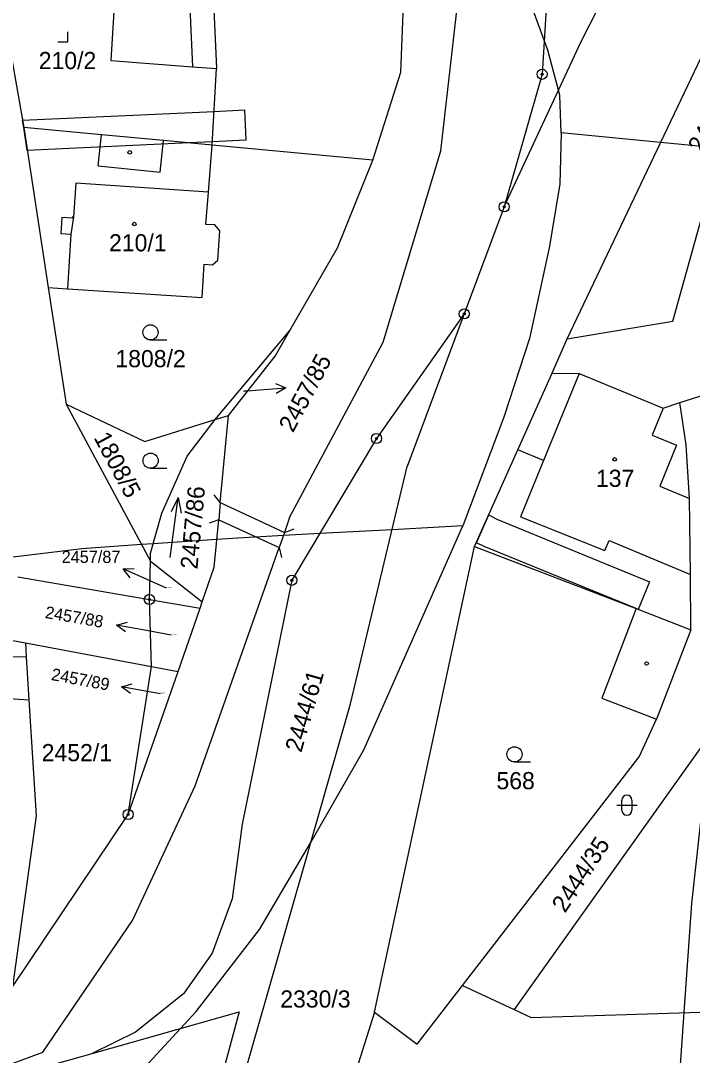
# Model space of a CAD drawing. Extents: x -546762 to -540209, y -1046851 to -1035694.
# Drawn here: x -542623.1 to -542556.7, y -1039379.4 to -1039277.1 of the extents above; entities that cross this region are included whole.
import ezdxf

# ---------------------------------------------------------------- set-up
doc = ezdxf.new("R2010")
doc.units = 0
for name, color, linetype in [('Vrstva 1', 7, 'Continuous'), ('Vrstva 16', 7, 'Continuous'), ('Vrstva 18', 7, 'Continuous'), ('Vrstva 19', 7, 'Continuous'), ('Vrstva 24', 7, 'Continuous'), ('Vrstva 25', 7, 'Continuous'), ('Vrstva 26', 7, 'Continuous'), ('Vrstva 3', 7, 'Continuous'), ('Vrstva 30', 7, 'Continuous'), ('Vrstva 37', 7, 'Continuous'), ('Vrstva 4', 7, 'Continuous'), ('Vrstva 52', 7, 'Continuous'), ('Vrstva 6', 7, 'Continuous')]:
    doc.layers.add(name, color=color, linetype=linetype)

msp = doc.modelspace()

# ---------------------------------------------------------------- linework, layer by layer
at = {"layer": 'Vrstva 1'}
for p, q in [((-542570.97, -1039273.17), (-542571.53, -1039282.43)), ((-542571.53, -1039282.43), (-542575.28, -1039295.54)), ((-542575.28, -1039295.54), (-542579.22, -1039306.11)), ((-542596.46, -1039307.75), (-542591.77, -1039299.59)), ((-542579.22, -1039306.11), (-542587.9, -1039318.45)), ((-542579.22, -1039306.11), (-542584.86, -1039321.23)), ((-542603.84, -1039316.58), (-542596.46, -1039307.75)), ((-542597.93, -1039310.3), (-542596.46, -1039307.75)), ((-542610.81, -1039318.73), (-542603.84, -1039316.58)), ((-542606.63, -1039320.18), (-542603.84, -1039316.58)), ((-542603.84, -1039316.58), (-542602.55, -1039316.18)), ((-542587.9, -1039318.45), (-542596.27, -1039332.47)), ((-542609.14, -1039325.83), (-542606.63, -1039320.18)), ((-542610.26, -1039329.78), (-542609.14, -1039325.83)), ((-542610.26, -1039330.56), (-542610.26, -1039329.78)), ((-542610.36, -1039334.36), (-542610.26, -1039330.56)), ((-542596.27, -1039332.47), (-542601.17, -1039356.59)), ((-542610.16, -1039340.99), (-542610.36, -1039334.36)), ((-542622.62, -1039338.66), (-542610.16, -1039340.99)), ((-542612.46, -1039355.63), (-542610.16, -1039340.99)), ((-542610.16, -1039340.99), (-542607.53, -1039341.48)), ((-542601.17, -1039356.59), (-542602.16, -1039363.96)), ((-542602.16, -1039363.96), (-542604.15, -1039369.33)), ((-542604.15, -1039369.33), (-542606.97, -1039373.35)), ((-542606.97, -1039373.35), (-542611.72, -1039377.16)), ((-542616.01, -1039379.25), (-542601.47, -1039375.13)), ((-542611.72, -1039377.16), (-542616.01, -1039379.25)), ((-542622.36, -1039381.05), (-542616.01, -1039379.25))]:
    msp.add_line(p, q, dxfattribs=at)
for points in [[(-542608.8, -1039221.77), (-542606.1, -1039281.68)], [(-542606, -1039231.49), (-542603.73, -1039281.85)], [(-542567.67, -1039279.19), (-542558.36, -1039260.91)], [(-542585.48, -1039282.22), (-542584.97, -1039268.84)], [(-542625.93, -1039269.87), (-542622.78, -1039287.69)], [(-542613.57, -1039271.3), (-542614.16, -1039281.08)], [(-542581.55, -1039290), (-542579.76, -1039274.36)], [(-542575.28, -1039295.54), (-542567.67, -1039279.19)], [(-542569.04, -1039308.59), (-542555.14, -1039279.37)], [(-542614.16, -1039281.08), (-542606.1, -1039281.68)], [(-542606.1, -1039281.68), (-542603.73, -1039281.85)], [(-542604.14, -1039289.43), (-542603.73, -1039281.85)], [(-542588.27, -1039290.91), (-542585.48, -1039282.22)], [(-542615.1, -1039288.41), (-542622.78, -1039287.69)], [(-542622.78, -1039287.69), (-542620.36, -1039303.51)], [(-542608.98, -1039288.98), (-542615.1, -1039288.41)], [(-542604.14, -1039289.43), (-542608.98, -1039288.98)], [(-542604.51, -1039294.08), (-542604.14, -1039289.43)], [(-542588.27, -1039290.91), (-542604.14, -1039289.43)], [(-542587.23, -1039308.93), (-542581.55, -1039290)], [(-542591.77, -1039299.59), (-542588.27, -1039290.91)], [(-542604.77, -1039297.27), (-542604.51, -1039294.08)], [(-542558.59, -1039306.85), (-542555.06, -1039294.18)], [(-542603.88, -1039297.32), (-542604.77, -1039297.27)], [(-542603.41, -1039297.91), (-542603.88, -1039297.32)], [(-542603.6, -1039300.8), (-542603.41, -1039297.91)], [(-542605.15, -1039304.51), (-542604.93, -1039301.21)], [(-542604.93, -1039301.21), (-542604.13, -1039301.27)], [(-542604.13, -1039301.27), (-542603.6, -1039300.8)], [(-542620.36, -1039303.51), (-542618.47, -1039303.63)], [(-542620.36, -1039303.51), (-542618.59, -1039315.06)], [(-542618.47, -1039303.63), (-542605.15, -1039304.51)], [(-542569.04, -1039308.59), (-542558.59, -1039306.85)], [(-542596.49, -1039326.27), (-542587.23, -1039308.93)], [(-542570.58, -1039312.06), (-542569.04, -1039308.59)], [(-542602.55, -1039316.18), (-542597.93, -1039310.3)], [(-542567.87, -1039312.03), (-542570.58, -1039312.06)], [(-542567.87, -1039312.03), (-542559.54, -1039315.43)], [(-542573.94, -1039319.58), (-542570.58, -1039312.06)], [(-542557.91, -1039314.9), (-542551.86, -1039312.96)], [(-542618.59, -1039315.06), (-542610.81, -1039318.73)], [(-542618.59, -1039315.06), (-542610.26, -1039330.56)], [(-542559.54, -1039315.43), (-542557.91, -1039314.9)], [(-542557.27, -1039319.06), (-542557.91, -1039314.9)], [(-542603.35, -1039324.79), (-542602.55, -1039316.18)], [(-542556.96, -1039324.37), (-542557.27, -1039319.06)], [(-542578.2, -1039329.14), (-542573.94, -1039319.58)], [(-542590.46, -1039344.67), (-542584.86, -1039321.23)], [(-542603.35, -1039324.79), (-542603.5, -1039326.48)], [(-542556.87, -1039331.9), (-542556.96, -1039324.37)], [(-542596.49, -1039326.27), (-542597, -1039327.73)], [(-542603.94, -1039331.18), (-542603.5, -1039326.48)], [(-542597, -1039327.73), (-542597.54, -1039329.24)], [(-542605.82, -1039352.79), (-542597.54, -1039329.24)], [(-542588.11, -1039375.18), (-542578.2, -1039329.14)], [(-542578.2, -1039329.14), (-542562.24, -1039335.27)], [(-542610.26, -1039330.56), (-542605.13, -1039334.59)], [(-542605.13, -1039334.59), (-542603.94, -1039331.18)], [(-542623.38, -1039332.13), (-542610.36, -1039334.36)], [(-542556.81, -1039337.35), (-542556.87, -1039331.9)], [(-542610.36, -1039334.36), (-542605.35, -1039335.22)], [(-542641.42, -1039335.16), (-542622.62, -1039338.66)], [(-542607.53, -1039341.48), (-542605.35, -1039335.22)], [(-542605.35, -1039335.22), (-542605.13, -1039334.59)], [(-542562.24, -1039335.27), (-542565.63, -1039344.11)], [(-542556.81, -1039337.35), (-542560.2, -1039346.19)], [(-542622.62, -1039338.66), (-542622.54, -1039340.03)], [(-542622.54, -1039340.03), (-542622.27, -1039344.3)], [(-542612.46, -1039355.63), (-542607.53, -1039341.48)], [(-542650.12, -1039342.4), (-542622.27, -1039344.3)], [(-542622.27, -1039344.3), (-542621.57, -1039355.75)], [(-542614.75, -1039429.6), (-542590.46, -1039344.67)], [(-542565.63, -1039344.11), (-542560.2, -1039346.19)], [(-542561.93, -1039349.93), (-542560.2, -1039346.19)], [(-542554.88, -1039347.66), (-542574.3, -1039374.91)], [(-542579.39, -1039372.53), (-542561.93, -1039349.93)], [(-542612.02, -1039366.12), (-542605.82, -1039352.79)], [(-542623.88, -1039372.67), (-542612.46, -1039355.63)], [(-542621.57, -1039355.75), (-542623.88, -1039372.67)], [(-542620.91, -1039379.14), (-542612.02, -1039366.12)], [(-542583.89, -1039378.35), (-542579.39, -1039372.53)], [(-542579.39, -1039372.53), (-542574.3, -1039374.91)], [(-542601.47, -1039375.13), (-542609.81, -1039406.08)], [(-542588.11, -1039375.18), (-542594.97, -1039396.88)], [(-542588.11, -1039375.18), (-542583.89, -1039378.35)], [(-542574.3, -1039374.91), (-542572.62, -1039375.69)], [(-542572.62, -1039375.69), (-542535.06, -1039374.51)], [(-542632.83, -1039383.53), (-542620.91, -1039379.14)]]:
    msp.add_lwpolyline(points, dxfattribs=at)
at = {"layer": 'Vrstva 16'}
for p, q in [((-542599.86, -1039313.67), (-542596.87, -1039313.44)), ((-542610.22, -1039332.56), (-542612.96, -1039331.34)), ((-542610.66, -1039337.44), (-542613.61, -1039336.91)), ((-542610.17, -1039343.53), (-542613.12, -1039343))]:
    msp.add_line(p, q, dxfattribs=at)
for points in [[(-542597.9, -1039313.02), (-542596.87, -1039313.44), (-542597.83, -1039314.01)], [(-542601.04, -1039313.76), (-542599.86, -1039313.67)], [(-542612.25, -1039332.21), (-542612.96, -1039331.34), (-542611.85, -1039331.29)], [(-542608.68, -1039333.24), (-542610.22, -1039332.56)], [(-542612.72, -1039337.58), (-542613.61, -1039336.91), (-542612.54, -1039336.6)], [(-542608.2, -1039337.88), (-542610.66, -1039337.44)], [(-542612.23, -1039343.67), (-542613.12, -1039343), (-542612.05, -1039342.69)], [(-542609.29, -1039343.69), (-542610.17, -1039343.53)]]:
    msp.add_lwpolyline(points, dxfattribs=at)
at = {"layer": 'Vrstva 24'}
for centre, radius in [((-542571.53, -1039282.43), 0.5), ((-542571.53, -1039282.43), 0.1), ((-542575.28, -1039295.54), 0.5), ((-542575.28, -1039295.54), 0.1), ((-542579.22, -1039306.11), 0.5), ((-542579.22, -1039306.11), 0.1), ((-542587.9, -1039318.45), 0.5), ((-542587.9, -1039318.45), 0.1), ((-542596.27, -1039332.47), 0.5), ((-542596.27, -1039332.47), 0.1), ((-542610.36, -1039334.36), 0.5), ((-542610.36, -1039334.36), 0.1), ((-542612.46, -1039355.63), 0.5), ((-542612.46, -1039355.63), 0.1)]:
    msp.add_circle(centre, radius, dxfattribs=at)
at = {"layer": 'Vrstva 25'}
for p, q in [((-542610.25, -1039308.7), (-542608.65, -1039308.7)), ((-542610.24, -1039321.39), (-542608.64, -1039321.39)), ((-542574.26, -1039350.43), (-542572.66, -1039350.43)), ((-542564.14, -1039354.7), (-542562.14, -1039354.7)), ((-542563.64, -1039355.2), (-542563.64, -1039354.2)), ((-542562.64, -1039354.2), (-542562.64, -1039355.2))]:
    msp.add_line(p, q, dxfattribs=at)
for points in [[(-542619.42, -1039279.22), (-542618.42, -1039279.22), (-542618.42, -1039278.22)], [(-542608.32, -1039330.21), (-542607.52, -1039324.27), (-542608.22, -1039325.69)], [(-542607.52, -1039324.27), (-542607.23, -1039325.82)]]:
    msp.add_lwpolyline(points, dxfattribs=at)
for centre, radius in [((-542612.3, -1039290.15), 0.175), ((-542611.85, -1039297.24), 0.175), ((-542610.25, -1039307.95), 0.75), ((-542610.24, -1039320.64), 0.75), ((-542564.36, -1039320.51), 0.175), ((-542561.19, -1039340.7), 0.175), ((-542574.26, -1039349.68), 0.75)]:
    msp.add_circle(centre, radius, dxfattribs=at)
for centre, start, end in [((-542563.14, -1039354.2), 0, 180), ((-542563.14, -1039355.2), 180, 0)]:
    msp.add_arc(centre, 0.5, start, end, dxfattribs=at)
at = {"layer": 'Vrstva 26'}
for p, q in [((-542603.35, -1039324.79), (-542603.96, -1039324)), ((-542603.5, -1039326.48), (-542604.44, -1039326.82)), ((-542597, -1039327.73), (-542596.06, -1039327.39)), ((-542597.54, -1039329.24), (-542597.29, -1039330.21))]:
    msp.add_line(p, q, dxfattribs=at)
at = {"layer": 'Vrstva 3'}
for points in [[(-542617.64, -1039293.21), (-542617.85, -1039296.56)], [(-542604.51, -1039294.08), (-542617.64, -1039293.21)], [(-542604.77, -1039297.27), (-542604.51, -1039294.08)], [(-542617.85, -1039296.56), (-542618.12, -1039298.24)], [(-542603.88, -1039297.32), (-542604.77, -1039297.27)], [(-542603.41, -1039297.91), (-542603.88, -1039297.32)], [(-542618.12, -1039298.24), (-542618.47, -1039303.63)], [(-542603.6, -1039300.8), (-542603.41, -1039297.91)], [(-542605.15, -1039304.51), (-542604.93, -1039301.21)], [(-542604.93, -1039301.21), (-542604.13, -1039301.27)], [(-542604.13, -1039301.27), (-542603.6, -1039300.8)], [(-542618.47, -1039303.63), (-542605.15, -1039304.51)], [(-542567.87, -1039312.03), (-542571.38, -1039320.63)], [(-542567.87, -1039312.03), (-542559.54, -1039315.43)], [(-542559.54, -1039315.43), (-542560.63, -1039318.12)], [(-542560.63, -1039318.12), (-542558.23, -1039319.1)], [(-542558.23, -1039319.1), (-542559.89, -1039323.17)], [(-542571.38, -1039320.63), (-542573.65, -1039326.18)], [(-542559.89, -1039323.17), (-542556.96, -1039324.37)], [(-542556.87, -1039331.9), (-542556.96, -1039324.37)], [(-542573.65, -1039326.18), (-542565.32, -1039329.53)], [(-542565.32, -1039329.53), (-542564.91, -1039328.53)], [(-542564.91, -1039328.53), (-542556.87, -1039331.9)]]:
    msp.add_lwpolyline(points, dxfattribs=at)
at = {"layer": 'Vrstva 30'}
for points in [[(-542600.95, -1039285.96), (-542600.81, -1039288.96), (-542604.12, -1039289.11), (-542606.41, -1039289.22), (-542622.43, -1039289.96), (-542622.78, -1039287.69), (-542622.91, -1039286.98), (-542603.96, -1039286.1), (-542600.95, -1039285.96)], [(-542576.01, -1039326.42), (-542560.91, -1039332.63), (-542562.03, -1039335.35), (-542562.24, -1039335.27), (-542577.27, -1039329.14), (-542578.03, -1039328.76), (-542576.81, -1039326.01), (-542576.01, -1039326.42)]]:
    msp.add_lwpolyline(points, dxfattribs=at)
at = {"layer": 'Vrstva 37'}
for centre in [(-542611.85, -1039297.24), (-542564.36, -1039320.51)]:
    msp.add_circle(centre, 0.175, dxfattribs=at)
at = {"layer": 'Vrstva 4'}
for points in [[(-542615.41, -1039291.49), (-542615.1, -1039288.41)], [(-542609.29, -1039292.11), (-542608.98, -1039288.98)], [(-542615.41, -1039291.49), (-542609.29, -1039292.11)], [(-542617.64, -1039293.21), (-542617.85, -1039296.56)], [(-542604.51, -1039294.08), (-542617.64, -1039293.21)], [(-542619.01, -1039296.58), (-542619.11, -1039298.18)], [(-542618.01, -1039296.65), (-542619.01, -1039296.58)], [(-542617.85, -1039296.56), (-542618.12, -1039298.24)], [(-542618, -1039296.55), (-542618.01, -1039296.65)], [(-542617.85, -1039296.56), (-542618, -1039296.55)], [(-542619.11, -1039298.18), (-542618.12, -1039298.24)], [(-542618.12, -1039298.24), (-542618.47, -1039303.63)], [(-542567.87, -1039312.03), (-542571.38, -1039320.63)], [(-542559.54, -1039315.43), (-542560.63, -1039318.12)], [(-542560.63, -1039318.12), (-542558.23, -1039319.1)], [(-542558.23, -1039319.1), (-542559.89, -1039323.17)], [(-542571.38, -1039320.63), (-542573.94, -1039319.58)], [(-542571.38, -1039320.63), (-542573.65, -1039326.18)], [(-542559.89, -1039323.17), (-542556.96, -1039324.37)], [(-542603.35, -1039324.79), (-542597, -1039327.73)], [(-542573.65, -1039326.18), (-542565.32, -1039329.53)], [(-542603.5, -1039326.48), (-542597.54, -1039329.24)], [(-542565.32, -1039329.53), (-542564.91, -1039328.53)], [(-542564.91, -1039328.53), (-542556.87, -1039331.9)], [(-542562.24, -1039335.27), (-542556.81, -1039337.35)]]:
    msp.add_lwpolyline(points, dxfattribs=at)
at = {"layer": 'Vrstva 52'}
for points in [[(-542569.64, -1039288.23), (-542569.79, -1039284.49), (-542569.92, -1039284.01), (-542570.96, -1039280.05), (-542571.33, -1039279.05), (-542574.88, -1039269.32), (-542579.84, -1039259.38), (-542582.74, -1039251.6), (-542584.03, -1039248.14), (-542585.59, -1039239.77), (-542586.05, -1039232.74), (-542584.75, -1039224.37), (-542583.96, -1039217.31), (-542580.82, -1039207.63), (-542577.81, -1039200.9), (-542577.43, -1039200.05), (-542572.98, -1039192.46), (-542566.81, -1039183.26), (-542561.58, -1039174.11), (-542558.14, -1039165.3), (-542558.11, -1039165.22)], [(-542569.64, -1039288.23), (-542569.79, -1039293.31), (-542570.84, -1039299.59), (-542572.78, -1039308.55), (-542575.32, -1039316.33), (-542579.35, -1039327.09)], [(-542545.54, -1039290.55), (-542546.85, -1039290.42), (-542547.26, -1039290.38), (-542552.34, -1039289.9), (-542559.81, -1039289.18), (-542569.64, -1039288.23)], [(-542559.32, -1039476.62), (-542559.51, -1039441.98), (-542559.57, -1039431.43), (-542559.58, -1039428.76), (-542559.41, -1039421.25), (-542558.98, -1039401.86), (-542558.8, -1039393.98), (-542557.47, -1039375.21), (-542556.71, -1039364.42), (-542554.87, -1039347.66), (-542554.61, -1039345.33), (-542552.78, -1039333.61), (-542551.22, -1039323.62), (-542550.86, -1039321.51), (-542549.39, -1039312.99), (-542545.57, -1039290.71), (-542545.54, -1039290.55)], [(-542579.35, -1039327.09), (-542586.35, -1039327.47), (-542593.51, -1039327.85), (-542597.11, -1039328.05), (-542601.61, -1039328.29), (-542603.68, -1039328.43), (-542610, -1039328.86), (-542611.13, -1039328.94), (-542617.03, -1039329.34), (-542623.55, -1039330.14), (-542625.57, -1039330.39), (-542629.84, -1039330.91), (-542630.16, -1039330.97), (-542645, -1039333.52), (-542647.3, -1039334.06), (-542661.73, -1039337.44), (-542671.71, -1039340.93), (-542678.2, -1039343.2), (-542682.91, -1039345.29), (-542689.52, -1039348.23), (-542691.93, -1039349.31), (-542701.72, -1039353.66), (-542708.45, -1039356.57)], [(-542612.01, -1039381.9), (-542607.29, -1039376.78), (-542605.74, -1039375.1), (-542599.46, -1039366.99), (-542594.37, -1039358.33), (-542594.23, -1039358.1), (-542589.17, -1039349.24), (-542579.35, -1039327.09)]]:
    msp.add_lwpolyline(points, dxfattribs=at)
at = {"layer": 'Vrstva 6'}
msp.add_lwpolyline([(-542642.06, -1039339.74), (-542622.54, -1039340.03)], dxfattribs=at)

# ---------------------------------------------------------------- texts
at = {"layer": 'Vrstva 16'}
for s, height, rotation, p in [('2457/85', 1.7, 61.8967, (-542596.16, -1039317.94)), ('2457/88', 1.2, 350.281, (-542620.74, -1039336.19)), ('2457/89', 1.2, 349.4147, (-542620.13, -1039342.32))]:
    msp.add_text(s, height=height, rotation=rotation, dxfattribs=at).set_placement(p)
msp.add_text('2457/87', height=1.2, dxfattribs=at).set_placement((-542619.03, -1039330.75))
at = {"layer": 'Vrstva 18'}
for s, rotation, p in [('2444/34', 60.8197, (-542555.72, -1039290.33)), ('1808/5', 298.2544, (-542615.9, -1039318.36)), ('2457/86', 84.6916, (-542605.61, -1039331.42)), ('2444/61', 74.0395, (-542595.34, -1039349.57)), ('2444/35', 56.7401, (-542569.26, -1039365.44))]:
    msp.add_text(s, height=1.7, rotation=rotation, dxfattribs=at).set_placement(p)
for s, height, p in [('1808/2', 1.7, (-542613.72, -1039311.4)), ('2457/85', 0.1, (-542601.04, -1039313.76)), ('2457/87', 0.1, (-542608.68, -1039333.24)), ('2457/88', 0.1, (-542608.2, -1039337.88)), ('2457/89', 0.1, (-542609.29, -1039343.69)), ('2452/1', 1.7, (-542621.01, -1039350.36)), ('568', 1.7, (-542576.04, -1039353.13)), ('2330/3', 1.7, (-542597.42, -1039374.72))]:
    msp.add_text(s, height=height, dxfattribs=at).set_placement(p)
at = {"layer": 'Vrstva 19'}
for s, p in [('210/2', (-542621.3, -1039281.92)), ('210/1', (-542614.35, -1039299.94)), ('137', (-542566.2, -1039323.23))]:
    msp.add_text(s, height=1.7, dxfattribs=at).set_placement(p)

doc.saveas('drawing.dxf')
